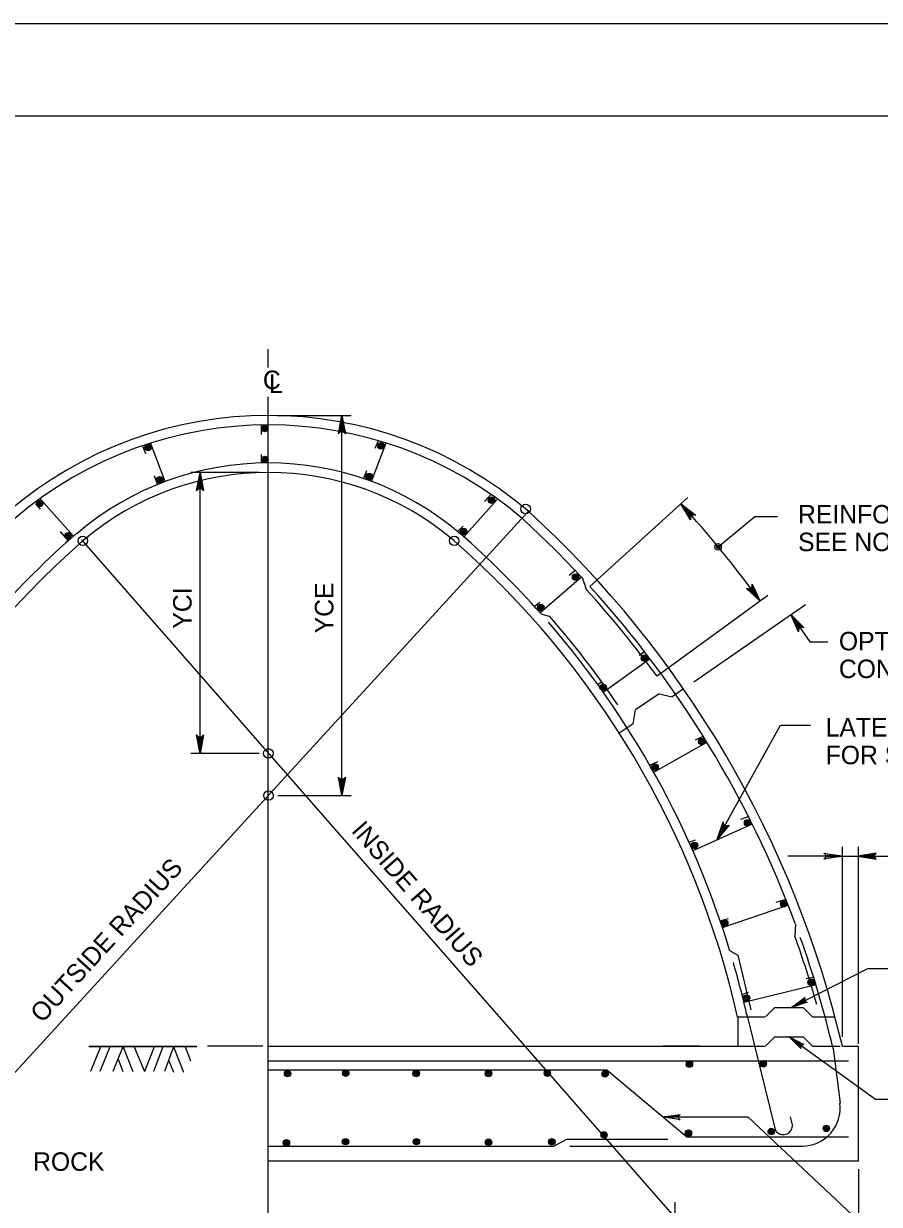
# Model space of a CAD drawing. Extents: x 639028 to 639883, y 298843 to 300031.
# Drawn here: x 639290.9 to 639429.9, y 299839.2 to 300031.1 of the extents above; entities that cross this region are included whole.
import ezdxf

# ---------------------------------------------------------------- set-up
doc = ezdxf.new("R2010")
doc.units = 0
for name, color, linetype in [('1', 7, 'Continuous'), ('2', 7, 'Continuous'), ('52', 7, 'Continuous'), ('PLT-BNDY', 7, 'Continuous')]:
    doc.layers.add(name, color=color, linetype=linetype)

# ---------------------------------------------------------------- blocks, each defined once
blk = doc.blocks.new('LT')
at = {"layer": '1'}
blk.add_lwpolyline([(0, 0), (-11.18, -2.1), (-10.75, -1.8), (-10.32, -1.5), (-10.1, -1.12), (-9.88, -0.75), (-9.81, -0.38), (-9.75, 0), (-9.81, 0.38), (-9.88, 0.75), (-10.1, 1.12), (-10.32, 1.5), (-10.75, 1.8), (-11.18, 2.1), (0, 0), (-10.75, 1.8), (-10.32, 1.5), (0, 0), (-10.1, 1.12), (-9.88, 0.75), (0, 0), (-9.81, 0.38), (-9.75, 0), (0, 0), (-9.81, -0.38), (-9.88, -0.75), (0, 0), (-10.1, -1.12), (-10.32, -1.5), (0, 0), (-10.75, -1.8)], dxfattribs=at)

msp = doc.modelspace()

# ---------------------------------------------------------------- linework, layer by layer
at = {"layer": '2'}
for p, q in [((639067.74, 300016.08), (639853.74, 300016.08)), ((639330.61, 299975.2), (639330.61, 299978.2)), ((639330.61, 299968.2), (639330.61, 299970.45)), ((639330.61, 299794.59), (639330.61, 299970.2)), ((639329.49, 299964.33), (639329.49, 299965.83)), ((639330.61, 299959.7), (639330.61, 299965.83)), ((639347.99, 299962.08), (639348.49, 299963.33)), ((639310.74, 299961.2), (639310.24, 299962.45)), ((639313.86, 299956.7), (639311.49, 299962.95)), ((639347.36, 299956.7), (639349.74, 299962.95)), ((639329.49, 299959.7), (639329.49, 299961.08)), ((639312.61, 299956.2), (639312.11, 299957.58)), ((639330.61, 299958.08), (639330.61, 299958.08)), ((639346.11, 299957.2), (639346.61, 299958.45)), ((639298.99, 299947.83), (639293.61, 299953.83)), ((639362.36, 299947.7), (639367.74, 299953.7)), ((639365.74, 299953.45), (639366.74, 299954.58)), ((639372.87, 299951.85), (639257.47, 299825.76)), ((639293.61, 299952.2), (639292.86, 299953.08)), ((639298.11, 299947.08), (639296.86, 299948.58)), ((639361.36, 299948.58), (639362.24, 299949.45)), ((639396.72, 299837.08), (639300.36, 299947.2)), ((639379.49, 299941.45), (639380.49, 299942.33)), ((639374.74, 299935.33), (639381.49, 299941.2)), ((639381.61, 299941.08), (639382.24, 299939.2)), ((639373.86, 299936.45), (639374.74, 299937.08)), ((639374.86, 299935.2), (639376.24, 299934.83)), ((639390.86, 299928.45), (639391.74, 299929.08)), ((639384.99, 299922.45), (639392.49, 299927.83)), ((639384.11, 299923.7), (639384.86, 299924.2)), ((639398.05, 299922.99), (639396.19, 299921.71)), ((639394.08, 299922.2), (639390.28, 299919.57)), ((639394.08, 299922.2), (639396.19, 299921.71)), ((639389.86, 299917.32), (639390.28, 299919.57)), ((639389.86, 299917.32), (639387.63, 299915.78)), ((639399.99, 299914.7), (639401.24, 299915.33)), ((639393.24, 299909.45), (639401.86, 299914.33)), ((639330.61, 299911.7), (639330.61, 299911.7)), ((639392.61, 299910.58), (639393.86, 299911.2)), ((639407.36, 299901.83), (639408.74, 299902.33)), ((639399.49, 299896.7), (639409.24, 299901.08)), ((639398.99, 299898.08), (639399.99, 299898.45)), ((639423.86, 299866.45), (639423.86, 299897.33)), ((639426.49, 299865.33), (639426.49, 299897.33)), ((639423.86, 299895.83), (639414.99, 299895.83)), ((639423.86, 299895.83), (639434.45, 299895.83)), ((639413.11, 299888.33), (639414.74, 299888.83)), ((639404.36, 299884.2), (639414.99, 299887.83)), ((639403.99, 299885.33), (639405.36, 299885.7)), ((639416.24, 299884.83), (639416.11, 299882.83)), ((639405.61, 299880.45), (639406.86, 299879.7)), ((639406.86, 299879.7), (639408.99, 299870.83)), ((639415.61, 299871.2), (639427.99, 299877.58)), ((639427.99, 299877.58), (639433.61, 299877.58)), ((639417.99, 299875.95), (639419.24, 299876.2)), ((639407.49, 299873.33), (639408.61, 299873.7)), ((639407.86, 299872.08), (639419.61, 299874.95)), ((639411.36, 299869.7), (639412.86, 299871.2)), ((639412.86, 299871.2), (639417.49, 299871.2)), ((639417.49, 299871.2), (639418.99, 299869.7)), ((639406.86, 299869.7), (639406.86, 299864.95)), ((639406.86, 299869.7), (639411.24, 299869.7)), ((639408.36, 299870.08), (639412.99, 299851.2)), ((639418.99, 299869.7), (639422.61, 299869.7)), ((639411.36, 299864.95), (639412.86, 299866.45)), ((639412.86, 299866.45), (639417.49, 299866.45)), ((639415.24, 299866.45), (639429.24, 299856.33)), ((639417.49, 299866.45), (639418.99, 299864.95)), ((639303.36, 299864.83), (639301.74, 299860.83)), ((639304.86, 299864.83), (639303.24, 299860.83)), ((639306.99, 299864.83), (639305.36, 299860.83)), ((639306.99, 299864.95), (639308.61, 299860.83)), ((639308.86, 299864.83), (639310.49, 299860.83)), ((639312.11, 299864.95), (639310.49, 299860.83)), ((639313.49, 299864.83), (639311.99, 299860.83)), ((639315.24, 299864.83), (639313.74, 299860.83)), ((639315.24, 299864.83), (639316.86, 299860.7)), ((639317.11, 299864.83), (639317.99, 299862.58)), ((639329.74, 299864.95), (639320.74, 299864.95)), ((639330.61, 299864.95), (639406.86, 299864.95)), ((639330.74, 299864.95), (639333.24, 299864.95)), ((639400.74, 299864.95), (639394.74, 299864.95)), ((639406.86, 299864.95), (639411.24, 299864.95)), ((639418.99, 299864.95), (639423.49, 299864.95)), ((639422.36, 299864.58), (639423.49, 299855.7)), ((639423.86, 299864.95), (639426.49, 299864.95)), ((639426.49, 299846.33), (639426.49, 299864.95)), ((639306.24, 299862.83), (639306.99, 299860.83)), ((639314.49, 299862.58), (639315.24, 299860.7)), ((639330.61, 299862.58), (639424.86, 299862.58)), ((639330.61, 299861.08), (639385.61, 299861.08)), ((639385.61, 299861.08), (639398.61, 299850.2)), ((639429.24, 299856.33), (639486.49, 299856.33)), ((639394.86, 299853.45), (639408.49, 299853.45)), ((639408.49, 299853.45), (639430.36, 299832.95)), ((639415.36, 299853.45), (639415.74, 299851.95)), ((639398.61, 299850.2), (639424.86, 299850.2)), ((639330.61, 299848.7), (639376.99, 299848.7)), ((639376.99, 299848.7), (639379.11, 299849.83)), ((639379.11, 299849.83), (639395.49, 299849.83)), ((639379.61, 299848.7), (639417.36, 299848.7)), ((639330.61, 299846.33), (639426.49, 299846.33)), ((639426.49, 299844.95), (639426.49, 299837.33)), ((639396.72, 299803.85), (639396.72, 299839.61))]:
    msp.add_line(p, q, dxfattribs=at)
for points in [[(639421, 299896.18), (639421.12, 299895.97), (639423.83, 299895.82), (639421, 299896.18), (639420.86, 299896.3), (639423.83, 299895.82), (639421.12, 299895.69), (639421.02, 299895.48), (639423.83, 299895.82), (639420.86, 299895.34), (639421.02, 299895.48)], [(639429.22, 299896.18), (639429.11, 299895.97), (639426.39, 299895.82), (639429.22, 299896.18), (639429.36, 299896.3), (639426.39, 299895.82), (639429.11, 299895.69), (639429.21, 299895.48), (639426.39, 299895.82), (639429.36, 299895.34), (639429.21, 299895.48)], [(639417.99, 299872.08), (639417.86, 299872.2), (639415.61, 299871.2), (639417.99, 299872.08), (639418.11, 299872.08), (639415.61, 299871.2), (639417.74, 299872.45), (639417.74, 299872.58), (639415.61, 299871.2), (639417.74, 299872.83), (639417.74, 299872.58)], [(639417.11, 299864.7), (639417.11, 299864.95), (639415.24, 299866.45), (639417.11, 299864.7), (639417.11, 299864.58), (639415.24, 299866.45), (639417.24, 299865.08), (639417.49, 299865.2), (639415.24, 299866.45), (639417.61, 299865.2), (639417.49, 299865.2)], [(639301.49, 299864.95), (639318.99, 299864.95)], [(639318.99, 299864.83), (639301.49, 299864.83)], [(639397.36, 299853.08), (639397.24, 299853.33), (639394.86, 299853.45), (639397.36, 299853.08), (639397.49, 299852.95), (639394.86, 299853.45), (639397.24, 299853.58), (639397.36, 299853.7), (639394.86, 299853.45), (639397.49, 299853.83), (639397.36, 299853.7)]]:
    msp.add_lwpolyline(points, dxfattribs=at)
for centre, radius in [((639330.02, 299965.29), 0.522), ((639330.01, 299965.3), 0.423), ((639330.01, 299965.3), 0.333), ((639330.01, 299965.31), 0.234), ((639330.01, 299965.29), 0.128), ((639330, 299965.3), 0.036), ((639311.09, 299962.21), 0.522), ((639311.09, 299962.21), 0.423), ((639311.09, 299962.21), 0.333), ((639311.09, 299962.22), 0.234), ((639311.09, 299962.2), 0.128), ((639311.08, 299962.21), 0.036), ((639348.91, 299962.48), 0.522), ((639348.91, 299962.49), 0.423), ((639348.91, 299962.49), 0.333), ((639348.91, 299962.5), 0.234), ((639348.91, 299962.48), 0.128), ((639348.9, 299962.49), 0.036), ((639330.08, 299960.27), 0.522), ((639330.08, 299960.28), 0.423), ((639330.08, 299960.28), 0.333), ((639330.08, 299960.28), 0.234), ((639330.08, 299960.27), 0.128), ((639330.07, 299960.28), 0.036), ((639347, 299957.51), 0.522), ((639347, 299957.51), 0.423), ((639347, 299957.51), 0.333), ((639347, 299957.52), 0.234), ((639347, 299957.5), 0.128), ((639346.99, 299957.51), 0.036), ((639313.01, 299956.96), 0.522), ((639313.01, 299956.96), 0.423), ((639313.01, 299956.96), 0.333), ((639313.01, 299956.97), 0.234), ((639313.01, 299956.95), 0.128), ((639313, 299956.96), 0.036), ((639366.87, 299953.64), 0.522), ((639366.87, 299953.65), 0.423), ((639366.87, 299953.65), 0.333), ((639366.87, 299953.66), 0.234), ((639366.87, 299953.64), 0.128), ((639366.86, 299953.65), 0.036), ((639293.48, 299953.09), 0.522), ((639293.48, 299953.1), 0.423), ((639293.48, 299953.1), 0.333), ((639293.48, 299953.11), 0.234), ((639293.48, 299953.09), 0.128), ((639293.47, 299953.1), 0.036), ((639372.42, 299952.21), 0.773), ((639298.09, 299947.88), 0.522), ((639298.09, 299947.88), 0.423), ((639298.09, 299947.88), 0.333), ((639298.09, 299947.89), 0.234), ((639298.09, 299947.87), 0.128), ((639298.08, 299947.88), 0.036), ((639362.32, 299948.55), 0.522), ((639362.32, 299948.55), 0.423), ((639362.32, 299948.55), 0.333), ((639362.32, 299948.56), 0.234), ((639362.32, 299948.55), 0.128), ((639362.31, 299948.55), 0.036), ((639300.49, 299947.05), 0.773), ((639360.81, 299947.05), 0.773), ((639380.52, 299941.16), 0.522), ((639380.51, 299941.17), 0.423), ((639380.51, 299941.17), 0.333), ((639380.51, 299941.18), 0.234), ((639380.51, 299941.16), 0.128), ((639380.51, 299941.17), 0.036), ((639374.87, 299936.2), 0.522), ((639374.87, 299936.21), 0.423), ((639374.87, 299936.21), 0.333), ((639374.87, 299936.22), 0.234), ((639374.87, 299936.2), 0.128), ((639374.86, 299936.21), 0.036), ((639391.72, 299927.97), 0.522), ((639391.72, 299927.98), 0.423), ((639391.72, 299927.98), 0.333), ((639391.72, 299927.99), 0.234), ((639391.72, 299927.97), 0.128), ((639391.71, 299927.98), 0.036), ((639385, 299923.24), 0.522), ((639385, 299923.25), 0.423), ((639385, 299923.25), 0.333), ((639385, 299923.26), 0.234), ((639385, 299923.24), 0.128), ((639384.99, 299923.25), 0.036), ((639401.03, 299914.45), 0.522), ((639401.03, 299914.46), 0.423), ((639401.03, 299914.46), 0.333), ((639401.03, 299914.47), 0.234), ((639401.03, 299914.45), 0.128), ((639401.02, 299914.46), 0.036), ((639330.63, 299912.51), 0.773), ((639393.44, 299910.27), 0.522), ((639393.44, 299910.28), 0.423), ((639393.44, 299910.28), 0.333), ((639393.44, 299910.29), 0.234), ((639393.44, 299910.27), 0.128), ((639393.43, 299910.28), 0.036), ((639330.65, 299905.67), 0.773), ((639408.46, 299901.22), 0.522), ((639408.46, 299901.23), 0.423), ((639408.46, 299901.23), 0.333), ((639408.46, 299901.24), 0.234), ((639408.46, 299901.22), 0.128), ((639408.45, 299901.23), 0.036), ((639399.84, 299897.56), 0.522), ((639399.84, 299897.57), 0.423), ((639399.84, 299897.57), 0.333), ((639399.84, 299897.57), 0.234), ((639399.84, 299897.56), 0.128), ((639399.83, 299897.57), 0.036), ((639414.32, 299888.08), 0.522), ((639414.32, 299888.09), 0.423), ((639414.32, 299888.09), 0.333), ((639414.32, 299888.1), 0.234), ((639414.32, 299888.08), 0.128), ((639414.31, 299888.09), 0.036), ((639404.75, 299884.94), 0.522), ((639404.75, 299884.94), 0.423), ((639404.75, 299884.94), 0.333), ((639404.75, 299884.95), 0.234), ((639404.75, 299884.94), 0.128), ((639404.74, 299884.94), 0.036), ((639418.78, 299875.32), 0.522), ((639418.78, 299875.33), 0.423), ((639418.78, 299875.33), 0.333), ((639418.78, 299875.34), 0.234), ((639418.78, 299875.32), 0.128), ((639418.77, 299875.33), 0.036), ((639408.28, 299872.76), 0.522), ((639408.27, 299872.77), 0.423), ((639408.27, 299872.77), 0.333), ((639408.27, 299872.77), 0.234), ((639408.27, 299872.76), 0.128), ((639408.27, 299872.77), 0.036), ((639399.01, 299862.03), 0.522), ((639399.01, 299862.04), 0.423), ((639399.01, 299862.04), 0.333), ((639399.01, 299862.05), 0.234), ((639399.01, 299862.03), 0.128), ((639399, 299862.04), 0.036), ((639411.02, 299862.08), 0.522), ((639411.02, 299862.08), 0.423), ((639411.02, 299862.08), 0.333), ((639411.02, 299862.09), 0.234), ((639411.02, 299862.08), 0.128), ((639411.01, 299862.08), 0.036), ((639333.75, 299860.47), 0.522), ((639333.75, 299860.48), 0.423), ((639333.75, 299860.48), 0.333), ((639333.75, 299860.49), 0.234), ((639333.75, 299860.47), 0.128), ((639333.74, 299860.48), 0.036), ((639343.19, 299860.55), 0.522), ((639343.18, 299860.56), 0.423), ((639343.18, 299860.56), 0.333), ((639343.18, 299860.57), 0.234), ((639343.18, 299860.55), 0.128), ((639343.18, 299860.56), 0.036), ((639354.63, 299860.5), 0.522), ((639354.63, 299860.51), 0.423), ((639354.63, 299860.51), 0.333), ((639354.63, 299860.52), 0.234), ((639354.63, 299860.5), 0.128), ((639354.62, 299860.51), 0.036), ((639366.38, 299860.5), 0.522), ((639366.38, 299860.51), 0.423), ((639366.38, 299860.51), 0.333), ((639366.38, 299860.52), 0.234), ((639366.38, 299860.5), 0.128), ((639366.37, 299860.51), 0.036), ((639375.94, 299860.55), 0.522), ((639375.94, 299860.56), 0.423), ((639375.94, 299860.56), 0.333), ((639375.94, 299860.57), 0.234), ((639375.94, 299860.55), 0.128), ((639375.93, 299860.56), 0.036), ((639385.31, 299860.43), 0.522), ((639385.31, 299860.44), 0.423), ((639385.31, 299860.44), 0.333), ((639385.31, 299860.44), 0.234), ((639385.31, 299860.43), 0.128), ((639385.3, 299860.44), 0.036), ((639421.25, 299851.58), 0.522), ((639421.25, 299851.58), 0.423), ((639385.14, 299850.52), 0.522), ((639385.14, 299850.53), 0.423), ((639385.14, 299850.53), 0.333), ((639385.14, 299850.54), 0.234), ((639385.14, 299850.52), 0.128), ((639385.13, 299850.53), 0.036), ((639398.85, 299850.81), 0.522), ((639398.84, 299850.82), 0.423), ((639398.84, 299850.82), 0.333), ((639398.84, 299850.83), 0.234), ((639398.84, 299850.81), 0.128), ((639398.84, 299850.82), 0.036), ((639412.31, 299851.06), 0.522), ((639412.3, 299851.07), 0.423), ((639412.3, 299851.07), 0.333), ((639412.3, 299851.07), 0.234), ((639412.3, 299851.06), 0.128), ((639412.3, 299851.07), 0.036), ((639421.25, 299851.58), 0.333), ((639421.25, 299851.59), 0.234), ((639421.25, 299851.58), 0.128), ((639421.24, 299851.58), 0.036), ((639333.56, 299849.24), 0.522), ((639333.55, 299849.25), 0.423), ((639333.55, 299849.25), 0.333), ((639333.55, 299849.26), 0.234), ((639333.55, 299849.24), 0.128), ((639333.55, 299849.25), 0.036), ((639343.16, 299849.42), 0.522), ((639343.15, 299849.43), 0.423), ((639343.15, 299849.43), 0.333), ((639343.15, 299849.44), 0.234), ((639343.15, 299849.42), 0.128), ((639343.14, 299849.43), 0.036), ((639354.68, 299849.42), 0.522), ((639354.68, 299849.43), 0.423), ((639354.68, 299849.43), 0.333), ((639354.68, 299849.44), 0.234), ((639354.68, 299849.42), 0.128), ((639354.67, 299849.43), 0.036), ((639366.38, 299849.33), 0.522), ((639366.38, 299849.34), 0.423), ((639366.38, 299849.34), 0.333), ((639366.38, 299849.35), 0.234), ((639366.38, 299849.33), 0.128), ((639366.37, 299849.34), 0.036), ((639376.66, 299849.41), 0.522), ((639376.65, 299849.42), 0.423), ((639376.65, 299849.42), 0.333), ((639376.65, 299849.43), 0.234), ((639376.65, 299849.41), 0.128), ((639376.64, 299849.42), 0.036)]:
    msp.add_circle(centre, radius, dxfattribs=at)
for centre, radius, start, end in [((639330.65, 299902.46), 64.97, 49.471, 130.5291), ((639330.65, 299902.46), 63.42, 49.471, 130.5291), ((639330.65, 299911.75), 47.95, 49.4891, 130.5174), ((639330.65, 299911.75), 46.41, 49.4891, 130.5174), ((639257.47, 299825.76), 170.93, 13.244, 47.5334), ((639257.47, 299825.76), 169.38, 42.8834, 47.5334), ((639396.78, 299837.11), 147.73, 131.215, 138.6042), ((639265, 299837.65), 146.95, 41.5988, 48.787), ((639396.82, 299837.07), 146.18, 131.215, 169.0167), ((639265, 299837.65), 145.41, 12.7116, 48.787), ((639257.47, 299825.76), 168.61, 36.0738, 42.283), ((639257.47, 299825.76), 169.38, 20.4297, 42.249), ((639265, 299837.65), 147.73, 34.0649, 41.1241), ((639265, 299837.65), 146.95, 16.9132, 40.8822), ((639257.47, 299825.76), 168.61, 15.81, 19.7727), ((639257.47, 299825.76), 169.38, 13.244, 19.6116), ((639265, 299837.65), 146.95, 12.7116, 16.1568), ((639417.32, 299854.9), 6.19, 270, 7.1233), ((639414.25, 299852.05), 1.47, 214.3089, 356.8636)]:
    msp.add_arc(centre, radius, start, end, dxfattribs=at)
at = {"layer": '52'}
for p, q in [((639332.11, 299967.43), (639344.07, 299967.43)), ((639342.57, 299905.67), (639342.57, 299967.43)), ((639329.11, 299958.16), (639318.04, 299958.16)), ((639319.54, 299912.51), (639319.54, 299958.16)), ((639398.77, 299954.1), (639382.85, 299939.64)), ((639411.76, 299938.16), (639393.75, 299925.04)), ((639399.75, 299924.16), (639417.88, 299936.71)), ((639329.13, 299912.51), (639318.04, 299912.51)), ((639332.15, 299905.67), (639344.07, 299905.67))]:
    msp.add_line(p, q, dxfattribs=at)
for points in [[(639397.62, 299953.06), (639400.04, 299951.23), (639399.91, 299951.26), (639399.77, 299951.29), (639399.66, 299951.27), (639399.54, 299951.24), (639399.46, 299951.19), (639399.37, 299951.13), (639399.31, 299951.05), (639399.25, 299950.97), (639399.21, 299950.86), (639399.18, 299950.75), (639399.2, 299950.61), (639399.21, 299950.47), (639397.62, 299953.06), (639399.2, 299950.61), (639399.18, 299950.75), (639397.62, 299953.06), (639399.21, 299950.86), (639399.25, 299950.97), (639397.62, 299953.06), (639399.31, 299951.05), (639399.37, 299951.13), (639397.62, 299953.06), (639399.46, 299951.19), (639399.54, 299951.24), (639397.62, 299953.06), (639399.66, 299951.27), (639399.77, 299951.29), (639397.62, 299953.06), (639399.91, 299951.26)], [(639403.66, 299946.08), (639409.63, 299950.98), (639413.31, 299950.98)], [(639410.5, 299937.24), (639408.3, 299939.32), (639408.43, 299939.28), (639408.56, 299939.23), (639408.67, 299939.24), (639408.79, 299939.25), (639408.88, 299939.3), (639408.97, 299939.34), (639409.04, 299939.42), (639409.11, 299939.49), (639409.16, 299939.6), (639409.21, 299939.7), (639409.2, 299939.84), (639409.2, 299939.98), (639410.5, 299937.24), (639409.2, 299939.84), (639409.21, 299939.7), (639410.5, 299937.24), (639409.16, 299939.6), (639409.11, 299939.49), (639410.5, 299937.24), (639409.04, 299939.42), (639408.97, 299939.34), (639410.5, 299937.24), (639408.88, 299939.3), (639408.79, 299939.25), (639410.5, 299937.24), (639408.67, 299939.24), (639408.56, 299939.23), (639410.5, 299937.24), (639408.43, 299939.28)], [(639415.49, 299935.05), (639418.56, 299930.64), (639421.48, 299930.64)], [(639415.49, 299935.05), (639417.65, 299932.92), (639417.52, 299932.97), (639417.39, 299933.02), (639417.27, 299933.01), (639417.16, 299933), (639417.06, 299932.96), (639416.97, 299932.92), (639416.9, 299932.85), (639416.83, 299932.78), (639416.78, 299932.67), (639416.73, 299932.56), (639416.73, 299932.42), (639416.73, 299932.28), (639415.49, 299935.05), (639416.73, 299932.42), (639416.73, 299932.56), (639415.49, 299935.05), (639416.78, 299932.67), (639416.83, 299932.78), (639415.49, 299935.05), (639416.9, 299932.85), (639416.97, 299932.92), (639415.49, 299935.05), (639417.06, 299932.96), (639417.16, 299933), (639415.49, 299935.05), (639417.27, 299933.01), (639417.39, 299933.02), (639415.49, 299935.05), (639417.52, 299932.97)], [(639403.52, 299898.51), (639413.82, 299917.08), (639418.67, 299917.08)], [(639403.52, 299898.51), (639404.48, 299901.39), (639404.49, 299901.25), (639404.51, 299901.12), (639404.57, 299901.01), (639404.63, 299900.91), (639404.7, 299900.85), (639404.78, 299900.79), (639404.88, 299900.75), (639404.98, 299900.72), (639405.09, 299900.72), (639405.21, 299900.73), (639405.33, 299900.79), (639405.46, 299900.85), (639403.52, 299898.51), (639405.33, 299900.79), (639405.21, 299900.73), (639403.52, 299898.51), (639405.09, 299900.72), (639404.98, 299900.72), (639403.52, 299898.51), (639404.88, 299900.75), (639404.78, 299900.79), (639403.52, 299898.51), (639404.7, 299900.85), (639404.63, 299900.91), (639403.52, 299898.51), (639404.57, 299901.01), (639404.51, 299901.12), (639403.52, 299898.51), (639404.49, 299901.25)]]:
    msp.add_lwpolyline(points, dxfattribs=at)
for radius in [0.533, 0.267]:
    msp.add_circle((639403.66, 299946.08), radius, dxfattribs=at)
msp.add_arc((639257.47, 299825.76), 189.34, 36.0738, 42.249, dxfattribs=at)
at = {"layer": 'PLT-BNDY'}
msp.add_lwpolyline([(639027.74, 300031.08), (639868.74, 300031.08), (639868.74, 299437.08), (639027.74, 299437.08)], close=True, dxfattribs=at)

# ---------------------------------------------------------------- block references
at = {"layer": '52', "xscale": 0.2682193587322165, "yscale": 0.26822435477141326}
for p, rotation in [((639342.57, 299967.43), 90), ((639319.54, 299958.16), 90), ((639319.54, 299912.51), -90), ((639342.57, 299905.67), -90)]:
    msp.add_blockref('LT', p, dxfattribs=dict(at, rotation=rotation))

# ---------------------------------------------------------------- texts
at = {"layer": '2'}
for s, p in [('C', (639329.74, 299971.7)), ('L', (639330.74, 299971.08)), ('REINFORCEMENT LAP SPLICE', (639416.66, 299949.87)), ('SEE NOTE 9', (639416.66, 299945.37)), ('OPTIONAL', (639423.29, 299929.25)), ('CONSTR. JT.', (639423.29, 299924.75)), ('LATERAL TIES AS REQUIRED', (639421.15, 299915.25)), ('FOR SHEAR #4 BARS @ 12" MAX.', (639421.15, 299910.75)), ('ROCK', (639292.42, 299844.69))]:
    msp.add_text(s, height=3, dxfattribs=at).set_placement(p)
for s, rotation, p in [('YCI', 90, (639318.16, 299932.78)), ('YCE', 90, (639341.19, 299932.02)), ('INSIDE RADIUS', 311.1859, (639343.97, 299899.87)), ('OUTSIDE RADIUS', 47.5862, (639293.91, 299868.57))]:
    msp.add_text(s, height=3, rotation=rotation, dxfattribs=at).set_placement(p)

doc.saveas('drawing.dxf')
